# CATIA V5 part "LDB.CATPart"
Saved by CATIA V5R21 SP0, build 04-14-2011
Part number: LDB.SLDPRT
Bounding box of the stored display mesh (mm): x 1.55 to 5.05, y 3.678 to 6.478, z -1.805 to -0.004
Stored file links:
  C:\Users\user\Desktop\CATIA文件\0-最新文件(2025.3月之前的慎用)\LDB\LDB.CATPart
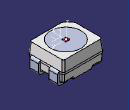
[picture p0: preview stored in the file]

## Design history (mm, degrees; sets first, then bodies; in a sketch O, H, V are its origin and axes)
AxisSystem1: origin (3.3012, 5.0712, -0.0046), X (0, -1, 0), Y (1, 0, 0), Z (0, 0, 1)
Set1
  DatumSurface1 to DatumSurface120
  Line1: stored without definition
  Circle1: stored without definition
  Line2: stored without definition
  Circle2: stored without definition
  Line3 to Line38: stored without definition
  Circle3: stored without definition
  Line39: stored without definition
  Circle4: stored without definition
  Line40 to Line43: stored without definition
  Circle5: stored without definition
  Circle6: stored without definition
  Line44 to Line46: stored without definition
  Circle7: stored without definition
  Line47: stored without definition
  Circle8: stored without definition
  Line48 to Line50: stored without definition
  Circle9 to Circle11: stored without definition
  Line51: stored without definition
  Circle12: stored without definition
  Line52: stored without definition
  Circle13 to Circle15: stored without definition
  Line53: stored without definition
  Circle16: stored without definition
  Line54: stored without definition
  Circle17 to Circle19: stored without definition
  Line55: stored without definition
  Circle20: stored without definition
  Line56: stored without definition
  Circle21 to Circle23: stored without definition
  Line57: stored without definition
  Circle24: stored without definition
  Line58: stored without definition
  Circle25: stored without definition
  Circle26: stored without definition
  Line59 to Line62: stored without definition
  Circle27: stored without definition
  Circle28: stored without definition
  Line63 to Line66: stored without definition
  Circle29: stored without definition
  Circle30: stored without definition
  Line67: stored without definition
  Circle31: stored without definition
  Line68: stored without definition
  Circle32: stored without definition
  Line69 to Line72: stored without definition
  Circle33: stored without definition
  Line73: stored without definition
  Circle34: stored without definition
  Circle35: stored without definition
  Line74: stored without definition
  Circle36: stored without definition
  Line75 to Line78: stored without definition
  Circle37: stored without definition
  Line79: stored without definition
  Circle38: stored without definition
  Line80 to Line82: stored without definition
  Circle39: stored without definition
  Line83: stored without definition
  Circle40: stored without definition
  Line84 to Line86: stored without definition
  Circle41: stored without definition
  Line87: stored without definition
  Circle42: stored without definition
  Line88 to Line90: stored without definition
  Circle43: stored without definition
  Line91: stored without definition
  Circle44: stored without definition
  Circle45: stored without definition
  Line92: stored without definition
  Circle46: stored without definition
  Line93 to Line95: stored without definition
  Circle47: stored without definition
  Line96: stored without definition
  Circle48: stored without definition
  Circle49: stored without definition
  Line97: stored without definition
  Circle50: stored without definition
  Line98 to Line100: stored without definition
  Circle51: stored without definition
  Line101: stored without definition
  Circle52: stored without definition
  Line102 to Line104: stored without definition
  Circle53: stored without definition
  Line105: stored without definition
  Circle54: stored without definition
  Line106 to Line108: stored without definition
  Circle55: stored without definition
  Line109: stored without definition
  Circle56: stored without definition
  Line110 to Line112: stored without definition
  Circle57: stored without definition
  Line113: stored without definition
  Circle58: stored without definition
  Line114: stored without definition
  Circle59: stored without definition
  Line115: stored without definition
  Circle60: stored without definition
  Line116 to Line118: stored without definition
  Circle61: stored without definition
  Line119: stored without definition
  Circle62: stored without definition
  Line120 to Line132: stored without definition
  Circle63: stored without definition
  Line133: stored without definition
  Circle64: stored without definition
  Line134 to Line136: stored without definition
  Circle65: stored without definition
  Line137: stored without definition
  Circle66: stored without definition
  Line138: stored without definition
  Circle67: stored without definition
  Line139: stored without definition
  Circle68: stored without definition
  Line140 to Line143: stored without definition
  Circle69: stored without definition
  Circle70: stored without definition
  Line144 to Line153: stored without definition
  Circle71: stored without definition
  Line154: stored without definition
  Circle72: stored without definition
  Line155 to Line157: stored without definition
  Circle73: stored without definition
  Line158: stored without definition
  Circle74: stored without definition
  Line159 to Line161: stored without definition
  Circle75: stored without definition
  Line162: stored without definition
  Circle76: stored without definition
  Line163 to Line165: stored without definition
  Circle77: stored without definition
  Line166: stored without definition
  Circle78: stored without definition
  Line167 to Line169: stored without definition
  Circle79: stored without definition
  Line170: stored without definition
  Circle80: stored without definition
  Line171 to Line173: stored without definition
  Circle81: stored without definition
  Line174: stored without definition
  Circle82: stored without definition
  Line175 to Line177: stored without definition
  Circle83: stored without definition
  Line178: stored without definition
  Circle84: stored without definition
  Line179 to Line181: stored without definition
  Circle85: stored without definition
  Line182: stored without definition
  Circle86: stored without definition
  Line183 to Line185: stored without definition
  Circle87: stored without definition
  Line186: stored without definition
  Circle88: stored without definition
  Line187 to Line189: stored without definition
  Circle89: stored without definition
  Line190: stored without definition
  Circle90: stored without definition
  Line191 to Line193: stored without definition
  Circle91: stored without definition
  Line194: stored without definition
  Circle92: stored without definition
  Line195 to Line197: stored without definition
  Circle93: stored without definition
  Line198: stored without definition
  Circle94: stored without definition
  Line199 to Line201: stored without definition
  Circle95: stored without definition
  Line202: stored without definition
  Circle96: stored without definition
  Line203 to Line205: stored without definition
  Circle97: stored without definition
  Line206: stored without definition
  Circle98: stored without definition
  Line207 to Line209: stored without definition
  Circle99: stored without definition
  Line210: stored without definition
  Circle100: stored without definition
  Line211 to Line213: stored without definition
  Circle101: stored without definition
  Line214: stored without definition
  Circle102: stored without definition
  Line215 to Line217: stored without definition
  Circle103: stored without definition
  Line218: stored without definition
  Circle104: stored without definition
  Line219 to Line221: stored without definition
  Circle105: stored without definition
  Line222: stored without definition
  Circle106: stored without definition
  Line223 to Line225: stored without definition
  Circle107: stored without definition
  Line226: stored without definition
  Circle108: stored without definition
  Line227 to Line229: stored without definition
  Circle109: stored without definition
  Line230: stored without definition
  Circle110: stored without definition
  Line231 to Line241: stored without definition
  DatumSurface121 to DatumSurface179
  Circle111: stored without definition
  Line242: stored without definition
  Circle112: stored without definition
  Line243: stored without definition
  Circle113 to Circle115: stored without definition
  Line244: stored without definition
  Circle116: stored without definition
  Line245 to Line248: stored without definition
  Circle117: stored without definition
  Circle118: stored without definition
  Line249 to Line251: stored without definition
  Circle119: stored without definition
  Line252: stored without definition
  Circle120: stored without definition
  Line253 to Line256: stored without definition
  Circle121: stored without definition
  Circle122: stored without definition
  Line257 to Line261: stored without definition
  Circle123: stored without definition
  Circle124: stored without definition
  Line262 to Line265: stored without definition
  Circle125 to Circle128: stored without definition
  Line266 to Line270: stored without definition
  Circle129: stored without definition
  Circle130: stored without definition
  Line271 to Line274: stored without definition
  Circle131: stored without definition
  Circle132: stored without definition
  Line275 to Line277: stored without definition
  Circle133: stored without definition
  Circle134: stored without definition
  Line278 to Line282: stored without definition
  Circle135: stored without definition
  Circle136: stored without definition
  Line283 to Line286: stored without definition
  Circle137: stored without definition
  Circle138: stored without definition
  Line287 to Line289: stored without definition
  Circle139: stored without definition
  Circle140: stored without definition
  Line290 to Line293: stored without definition
  Circle141: stored without definition
  Circle142: stored without definition
  Line294 to Line298: stored without definition
  Circle143: stored without definition
  Circle144: stored without definition
  Line299 to Line302: stored without definition
  Circle145: stored without definition
  Circle146: stored without definition
  Line303 to Line306: stored without definition
  Circle147: stored without definition
  Circle148: stored without definition
  Line307 to Line310: stored without definition
  Circle149: stored without definition
  Circle150: stored without definition
  Line311: stored without definition
  Circle151: stored without definition
  Line312: stored without definition
  Circle152 to Circle154: stored without definition
  Line313 to Line316: stored without definition
  Circle155: stored without definition
  Circle156: stored without definition
  Line317 to Line320: stored without definition
  Circle157: stored without definition
  Circle158: stored without definition
  Line321: stored without definition
  Line322: stored without definition
  Circle159: stored without definition
  Circle160: stored without definition
  Line323 to Line325: stored without definition
  Circle161: stored without definition
  Circle162: stored without definition
  Line326 to Line330: stored without definition
  Circle163: stored without definition
  Circle164: stored without definition
  Line331 to Line334: stored without definition
  Circle165: stored without definition
  Circle166: stored without definition
  Line335 to Line337: stored without definition
  Circle167: stored without definition
  Circle168: stored without definition
  Line338 to Line342: stored without definition
  Circle169: stored without definition
  Line343 to Line345: stored without definition
  Circle170: stored without definition
  Line346 to Line352: stored without definition
  DatumSurface180 to DatumSurface390
  Circle171: stored without definition
  Circle172: stored without definition
  Line353: stored without definition
  Line354: stored without definition
  Circle173: stored without definition
  Circle174: stored without definition
  DatumCurve1
  Line355: stored without definition
  Line356: stored without definition
  Circle175: stored without definition
  Line357: stored without definition
  DatumCurve2
  Circle176: stored without definition
  Line358: stored without definition
  Circle177 to Circle183: stored without definition
  Line359: stored without definition
  Line360: stored without definition
  Circle184 to Circle188: stored without definition
  Line361: stored without definition
  Circle189: stored without definition
  Line362: stored without definition
  Circle190 to Circle192: stored without definition
  Line363: stored without definition
  Circle193: stored without definition
  Line364: stored without definition
  Circle194 to Circle196: stored without definition
  Line365: stored without definition
  Circle197: stored without definition
  Line366: stored without definition
  Circle198 to Circle200: stored without definition
  Line367: stored without definition
  Circle201: stored without definition
  Line368: stored without definition
  Circle202 to Circle204: stored without definition
  Line369 to Line373: stored without definition
  Circle205: stored without definition
  Line374: stored without definition
  Circle206 to Circle208: stored without definition
  Line375: stored without definition
  Circle209: stored without definition
  Line376: stored without definition
  Circle210: stored without definition
  Line377 to Line379: stored without definition
  Circle211: stored without definition
  Circle212: stored without definition
  Line380 to Line383: stored without definition
  Circle213: stored without definition
  Circle214: stored without definition
  Line384 to Line388: stored without definition
  Circle215: stored without definition
  Circle216: stored without definition
  Line389 to Line391: stored without definition
  Circle217: stored without definition
  Circle218: stored without definition
  Line392: stored without definition
  Line393: stored without definition
  Circle219: stored without definition
  Circle220: stored without definition
  Line394 to Line397: stored without definition
  Circle221: stored without definition
  Circle222: stored without definition
  Line398 to Line401: stored without definition
  Circle223 to Circle226: stored without definition
  Line402 to Line405: stored without definition
  Circle227: stored without definition
  Circle228: stored without definition
  Line406 to Line409: stored without definition
  Circle229: stored without definition
  Circle230: stored without definition
  Line410 to Line413: stored without definition
  Circle231: stored without definition
  Circle232: stored without definition
  Line414 to Line417: stored without definition
  Circle233: stored without definition
  Circle234: stored without definition
  Line418 to Line422: stored without definition
  Circle235: stored without definition
  Circle236: stored without definition
  Line423 to Line426: stored without definition
  Circle237: stored without definition
  Circle238: stored without definition
  Line427 to Line429: stored without definition
  Circle239: stored without definition
  Circle240: stored without definition
  Line430 to Line433: stored without definition
  Circle241: stored without definition
  Circle242: stored without definition
  Line434 to Line438: stored without definition
  Circle243: stored without definition
  Circle244: stored without definition
  Line439 to Line441: stored without definition
  Circle245: stored without definition
  Circle246: stored without definition
  Line442 to Line445: stored without definition
  Circle247: stored without definition
  Circle248: stored without definition
  Line446 to Line450: stored without definition
  Circle249 to Circle252: stored without definition
  Line451 to Line454: stored without definition
  Circle253: stored without definition
  Circle254: stored without definition
  Line455 to Line459: stored without definition
  Circle255 to Circle257: stored without definition
  Line460: stored without definition
  Circle258: stored without definition
  Line461 to Line464: stored without definition
  Circle259: stored without definition
  Line465: stored without definition
  Circle260: stored without definition
  Line466 to Line468: stored without definition
  Circle261: stored without definition
  Line469: stored without definition
  Circle262: stored without definition
  Line470 to Line472: stored without definition
  Circle263: stored without definition
  Line473: stored without definition
  Circle264: stored without definition
  Line474 to Line476: stored without definition
  Circle265: stored without definition
  Line477: stored without definition
  Circle266: stored without definition
  Line478 to Line480: stored without definition
  Circle267: stored without definition
  Line481: stored without definition
  Circle268: stored without definition
  Line482 to Line484: stored without definition
  Circle269: stored without definition
  Line485: stored without definition
  Circle270: stored without definition
  Line486 to Line488: stored without definition
  Circle271: stored without definition
  Line489: stored without definition
  Circle272: stored without definition
  Line490 to Line492: stored without definition
  Circle273: stored without definition
  Line493: stored without definition
  Circle274: stored without definition
  Line494 to Line496: stored without definition
  Circle275: stored without definition
  Line497: stored without definition
  Circle276: stored without definition
  Line498 to Line500: stored without definition
  Circle277: stored without definition
  Line501: stored without definition
  Circle278: stored without definition
  Line502 to Line509: stored without definition
  Circle279: stored without definition
  Circle280: stored without definition
  DatumCurve3
  DatumCurve4
  Circle281: stored without definition
  Line510 to Line512: stored without definition
  DatumCurve5
  Circle282: stored without definition
  Circle283: stored without definition
  DatumCurve6
  DatumCurve7
  Line513: stored without definition
  DatumCurve8
  Line514: stored without definition
  Circle284: stored without definition
  DatumCurve9
  Circle285: stored without definition
  Line515: stored without definition
  Circle286: stored without definition
  Line516: stored without definition
  DatumCurve10
  Circle287: stored without definition
  Circle288: stored without definition
  Line517: stored without definition
  Line518: stored without definition
  DatumCurve11
  Circle289: stored without definition
  DatumCurve12
  Line519: stored without definition
  Circle290: stored without definition
  Line520: stored without definition
  DatumCurve13
  Circle291: stored without definition
  Line521: stored without definition
  Circle292: stored without definition
  Line522: stored without definition
  Line523: stored without definition
  Circle293: stored without definition
  Line524: stored without definition
  DatumCurve14
  Circle294: stored without definition
  Line525: stored without definition
  Line526: stored without definition
  Circle295: stored without definition
  Circle296: stored without definition
  Line527 to Line529: stored without definition
  DatumCurve15
  Line530: stored without definition
  Circle297: stored without definition
  DatumCurve16
  Line531: stored without definition
  Circle298: stored without definition
  Line532: stored without definition
  Line533: stored without definition
  DatumCurve17
  Circle299: stored without definition
  Line534: stored without definition
  Line535: stored without definition
  Circle300: stored without definition
  Circle301: stored without definition
  Line536: stored without definition
  Line537: stored without definition
  Circle302: stored without definition
  Line538: stored without definition
  Circle303: stored without definition
  Line539 to Line542: stored without definition
  DatumCurve18
  Line543: stored without definition
  DatumCurve19
  Circle304: stored without definition
  DatumCurve20
  Line544: stored without definition
  Circle305: stored without definition
  Line545: stored without definition
  DatumCurve21
  DatumCurve22
  Line546: stored without definition
  Circle306 to Circle308: stored without definition
  Line547: stored without definition
  Circle309: stored without definition
  Line548: stored without definition
  Line549: stored without definition
  DatumCurve23
  Line550 to Line555: stored without definition
  Circle310: stored without definition
  Line556: stored without definition
  Circle311: stored without definition
  Line557 to Line559: stored without definition
  Circle312: stored without definition
  Line560: stored without definition
  Circle313: stored without definition
  Line561 to Line580: stored without definition
  Circle314: stored without definition
  Line581: stored without definition
  DatumCurve24
  Line582: stored without definition
  DatumCurve25
  Line583 to Line588: stored without definition
  Circle315: stored without definition
  Line589: stored without definition
  Circle316: stored without definition
  Line590 to Line592: stored without definition
  Circle317: stored without definition
  Line593: stored without definition
  Circle318: stored without definition
  Line594 to Line596: stored without definition
  Circle319: stored without definition
  Line597: stored without definition
  Circle320: stored without definition
  Line598 to Line600: stored without definition
  Circle321: stored without definition
  Line601: stored without definition
  Circle322: stored without definition
  Line602 to Line604: stored without definition
  Circle323: stored without definition
  Line605: stored without definition
  Circle324: stored without definition
  Circle325: stored without definition
  Line606: stored without definition
  Circle326: stored without definition
  Line607 to Line609: stored without definition
  Circle327: stored without definition
  Line610: stored without definition
  Circle328: stored without definition
  Circle329: stored without definition
  Line611: stored without definition
  Circle330: stored without definition
  Line612 to Line614: stored without definition
  Circle331: stored without definition
  Line615: stored without definition
  Circle332: stored without definition
  Line616 to Line618: stored without definition
  Circle333: stored without definition
  Line619: stored without definition
  Circle334: stored without definition
  Line620 to Line622: stored without definition
  Circle335: stored without definition
  Line623: stored without definition
  Circle336: stored without definition
  Line624 to Line626: stored without definition
  Circle337: stored without definition
  Line627: stored without definition
  Circle338: stored without definition
  Line628 to Line634: stored without definition
  Circle339: stored without definition
  DatumCurve26
  Line635: stored without definition
  DatumCurve27
  Line636: stored without definition
  Line637: stored without definition
  DatumCurve28
  Line638: stored without definition
  DatumCurve29
  Circle340: stored without definition
  Line639: stored without definition
  DatumCurve30
  Line640 to Line642: stored without definition
  DatumCurve31
  Line643 to Line645: stored without definition
  DatumCurve32
  Circle341: stored without definition
  Line646 to Line650: stored without definition
  DatumCurve33
  Circle342: stored without definition
  Line651 to Line664: stored without definition
  Circle343: stored without definition
  Line665: stored without definition
  Circle344: stored without definition
  Line666: stored without definition
  Circle345: stored without definition
  Line667: stored without definition
  Circle346: stored without definition
  Line668: stored without definition
  Circle347: stored without definition
  Line669: stored without definition
  Circle348: stored without definition
  Line670: stored without definition
  Circle349: stored without definition
  DatumCurve34
  Line671 to Line674: stored without definition
  Circle350: stored without definition
  Line675 to Line677: stored without definition
  Circle351: stored without definition
  Line678: stored without definition
  Line679: stored without definition
  Circle352: stored without definition
  Line680 to Line683: stored without definition
  Circle353: stored without definition
  Line684: stored without definition
  Line685: stored without definition
  Circle354: stored without definition
  Line686 to Line688: stored without definition
  Circle355: stored without definition
  Line689 to Line692: stored without definition
  Circle356: stored without definition
  Line693 to Line702: stored without definition
  DatumCurve35
  Line703: stored without definition
  DatumCurve36
  Circle357: stored without definition
  Line704: stored without definition
  Line705: stored without definition
  Circle358: stored without definition
  Line706 to Line713: stored without definition
  Point1 "发光中心&几何中心（测试原点）": type Center, Curve edge of DatumSurface344
  Point2 "虚拟坐标": (0.0052, -0.0007, -0.1333), relative to Point1, in AxisSystem1
Body1 (main body)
